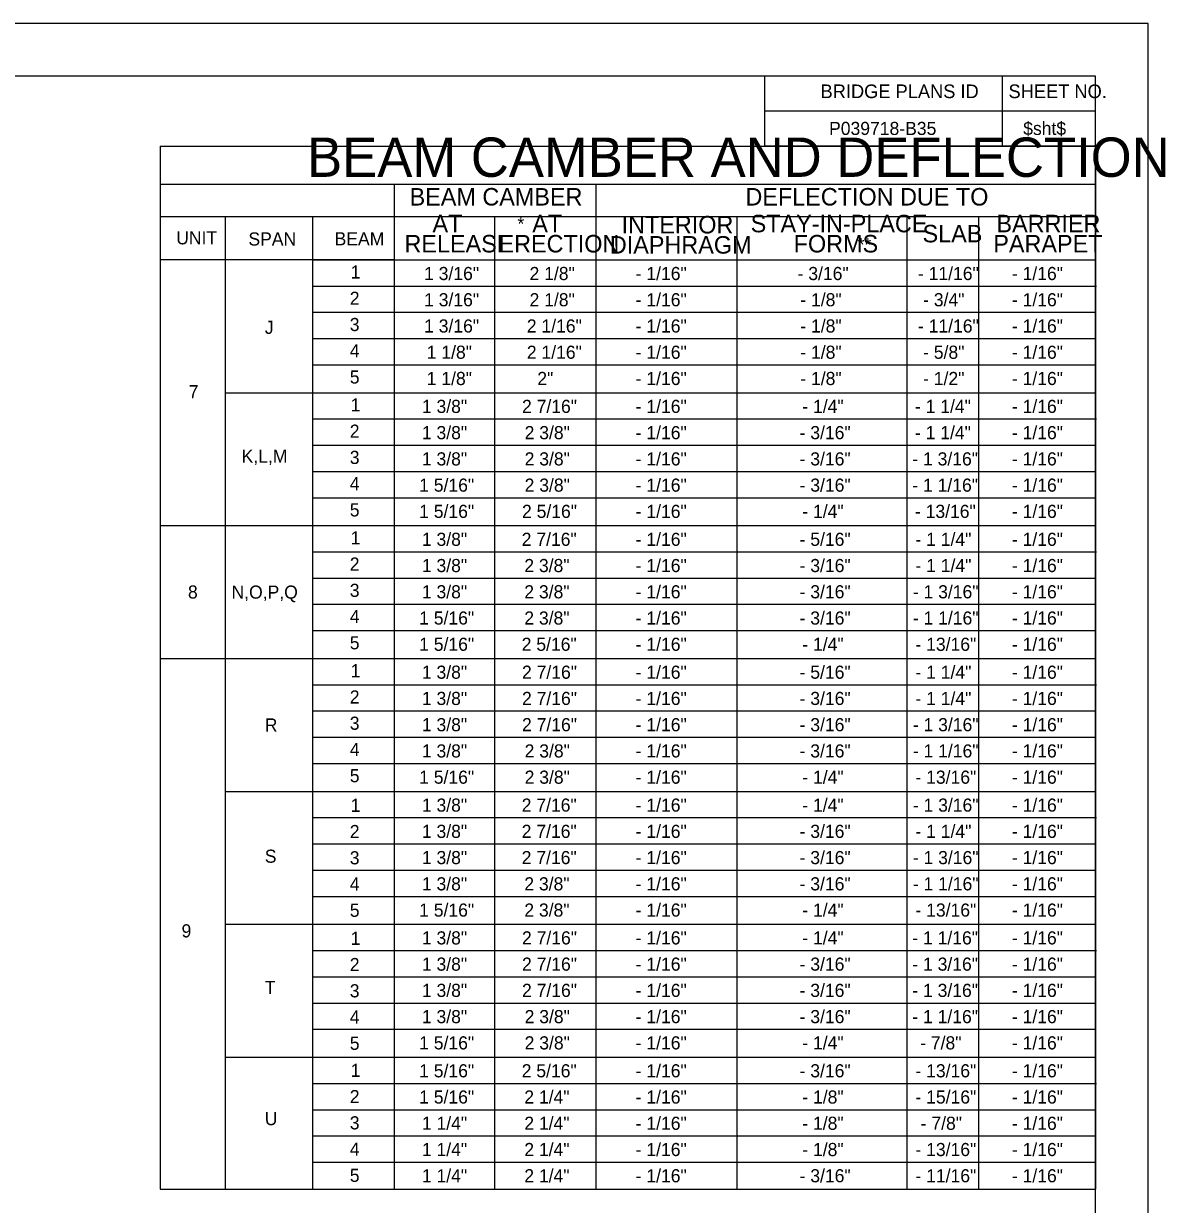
# Model space of a CAD drawing. Extents: x -50.5 to -14.4, y -5.1 to 16.9.
# Drawn here: x -25.23 to -14.35, y 5.69 to 16.93 of the extents above; entities that cross this region are included whole.
import ezdxf

# ---------------------------------------------------------------- set-up
doc = ezdxf.new("R2010")
doc.units = 0
for name, color, linetype in [('BR_BORDER LINES', 7, 'Continuous'), ('BR_TABLE LINES', 7, 'Continuous'), ('BR_TEXT', 7, 'Continuous'), ('Level 31', 7, 'Continuous')]:
    doc.layers.add(name, color=color, linetype=linetype)

msp = doc.modelspace()

# ---------------------------------------------------------------- linework, layer by layer
at = {"layer": 'BR_BORDER LINES'}
for p, q in [((-15.019, 16.434), (-48.685, 16.434)), ((-18.172, 15.767), (-18.172, 16.434)), ((-15.905, 15.767), (-15.905, 16.434)), ((-15.019, -4.566), (-15.019, 16.434)), ((-18.172, 16.104), (-15.019, 16.104)), ((-15.905, 16.104), (-15.019, 16.104)), ((-23.933, 15.767), (-15.019, 15.767)), ((-23.933, 15.767), (-23.933, 5.832)), ((-15.019, 15.767), (-18.172, 15.767)), ((-15.019, 15.767), (-15.019, 5.832)), ((-23.933, 15.403), (-15.019, 15.403)), ((-23.933, 5.832), (-15.019, 5.832))]:
    msp.add_line(p, q, dxfattribs=at)
at = {"layer": 'BR_TABLE LINES'}
for p, q in [((-21.704, 15.403), (-21.704, 5.832)), ((-19.78, 15.403), (-19.78, 5.832)), ((-23.933, 15.095), (-15.019, 15.095)), ((-23.313, 15.095), (-23.313, 5.832)), ((-22.481, 15.095), (-22.481, 5.832)), ((-20.747, 15.095), (-20.747, 5.832)), ((-18.439, 15.095), (-18.439, 5.832)), ((-16.818, 15.095), (-16.818, 5.832)), ((-16.136, 15.095), (-16.136, 5.832)), ((-21.704, 14.684), (-23.933, 14.684)), ((-22.481, 14.684), (-15.019, 14.684)), ((-22.481, 14.434), (-15.011, 14.434)), ((-22.481, 14.184), (-15.019, 14.184)), ((-22.481, 13.934), (-15.019, 13.934)), ((-22.481, 13.684), (-15.019, 13.684)), ((-23.313, 13.418), (-15.019, 13.418)), ((-22.481, 13.168), (-15.011, 13.168)), ((-22.481, 12.918), (-15.019, 12.918)), ((-22.481, 12.668), (-15.019, 12.668)), ((-22.481, 12.418), (-15.019, 12.418)), ((-23.933, 12.152), (-15.019, 12.152)), ((-22.481, 11.902), (-15.011, 11.902)), ((-22.481, 11.652), (-15.019, 11.652)), ((-22.481, 11.402), (-15.019, 11.402)), ((-22.481, 11.152), (-15.019, 11.152)), ((-23.933, 10.886), (-15.019, 10.886)), ((-22.481, 10.636), (-15.011, 10.636)), ((-22.481, 10.386), (-15.019, 10.386)), ((-22.481, 10.136), (-15.019, 10.136)), ((-22.481, 9.886), (-15.019, 9.886)), ((-23.313, 9.62), (-15.019, 9.62)), ((-22.481, 9.37), (-15.011, 9.37)), ((-22.481, 9.12), (-15.019, 9.12)), ((-22.481, 8.87), (-15.019, 8.87)), ((-22.481, 8.62), (-15.019, 8.62)), ((-23.313, 8.354), (-15.019, 8.354)), ((-22.481, 8.104), (-15.011, 8.104)), ((-22.481, 7.854), (-15.019, 7.854)), ((-22.481, 7.604), (-15.019, 7.604)), ((-22.481, 7.354), (-15.019, 7.354)), ((-23.313, 7.088), (-15.019, 7.088)), ((-22.481, 6.838), (-15.011, 6.838)), ((-22.481, 6.588), (-15.019, 6.588)), ((-22.481, 6.338), (-15.019, 6.338)), ((-22.481, 6.088), (-15.019, 6.088))]:
    msp.add_line(p, q, dxfattribs=at)
at = {"layer": 'Level 31'}
msp.add_lwpolyline([(-50.519, -5.066), (-14.519, -5.066), (-14.519, 16.934), (-50.519, 16.934)], close=True, dxfattribs=at)

# ---------------------------------------------------------------- texts
at = {"layer": 'BR_TEXT'}
for s, height, p in [('BRIDGE PLANS ID', 0.13, (-17.64, 16.224)), ('SHEET NO.', 0.13, (-15.849, 16.224)), ('P039718-B35', 0.125, (-17.559, 15.873)), ('$sht$', 0.125, (-15.709, 15.873)), ('BEAM CAMBER AND DEFLECTION', 0.375, (-22.533, 15.474)), ('BEAM CAMBER', 0.16667, (-21.556, 15.201)), ('DEFLECTION DUE TO', 0.16667, (-18.356, 15.201)), ('AT', 0.1667, (-21.338, 14.946)), ('*', 0.125, (-20.528, 14.964)), ('AT', 0.1667, (-20.387, 14.946)), ('INTERIOR', 0.1667, (-19.536, 14.935)), ('STAY-IN-PLACE', 0.16667, (-18.306, 14.946)), ('BARRIER', 0.1667, (-15.964, 14.946)), ('SLAB', 0.1667, (-16.668, 14.85)), ('RELEASE', 0.1667, (-21.605, 14.754)), ('ERECTION', 0.1667, (-20.709, 14.754)), ('DIAPHRAGM', 0.1667, (-19.648, 14.743)), ('FORMS', 0.1667, (-17.896, 14.754)), ('**', 0.125, (-17.287, 14.766)), ('PARAPET', 0.1667, (-15.994, 14.754)), ('1', 0.125, (-22.118, 14.505)), ('1 3/16"', 0.125, (-21.418, 14.491)), ('2 1/8"', 0.125, (-20.413, 14.491)), ('- 1/16"', 0.125, (-19.402, 14.491)), ('- 3/16"', 0.125, (-17.859, 14.491)), ('- 11/16"', 0.125, (-16.712, 14.491)), ('- 1/16"', 0.125, (-15.817, 14.491)), ('2', 0.125, (-22.126, 14.255)), ('1 3/16"', 0.125, (-21.418, 14.241)), ('2 1/8"', 0.125, (-20.413, 14.241)), ('- 1/16"', 0.125, (-19.402, 14.241)), ('- 1/8"', 0.125, (-17.833, 14.241)), ('- 3/4"', 0.125, (-16.663, 14.241)), ('- 1/16"', 0.125, (-15.817, 14.241)), ('3', 0.125, (-22.126, 14.005)), ('1 3/16"', 0.125, (-21.418, 13.991)), ('2 1/16"', 0.125, (-20.439, 13.991)), ('- 1/16"', 0.125, (-19.402, 13.991)), ('- 1/8"', 0.125, (-17.833, 13.991)), ('- 11/16"', 0.125, (-16.712, 13.991)), ('- 1/16"', 0.125, (-15.817, 13.991)), ('4', 0.125, (-22.126, 13.755)), ('1 1/8"', 0.125, (-21.393, 13.741)), ('2 1/16"', 0.125, (-20.439, 13.741)), ('- 1/16"', 0.125, (-19.402, 13.741)), ('- 1/8"', 0.125, (-17.833, 13.741)), ('- 5/8"', 0.125, (-16.663, 13.741)), ('- 1/16"', 0.125, (-15.817, 13.741)), ('5', 0.125, (-22.126, 13.505)), ('1 1/8"', 0.125, (-21.393, 13.491)), ('2"', 0.125, (-20.339, 13.491)), ('- 1/16"', 0.125, (-19.402, 13.491)), ('- 1/8"', 0.125, (-17.833, 13.491)), ('- 1/2"', 0.125, (-16.663, 13.491)), ('- 1/16"', 0.125, (-15.817, 13.491)), ('1', 0.125, (-22.118, 13.239)), ('1 3/8"', 0.125, (-21.439, 13.225)), ('2 7/16"', 0.125, (-20.485, 13.225)), ('- 1/16"', 0.125, (-19.402, 13.225)), ('- 1/4"', 0.125, (-17.814, 13.225)), ('- 1 1/4"', 0.125, (-16.741, 13.225)), ('- 1/16"', 0.125, (-15.817, 13.225)), ('2', 0.125, (-22.126, 12.989)), ('1 3/8"', 0.125, (-21.439, 12.975)), ('2 3/8"', 0.125, (-20.46, 12.975)), ('- 1/16"', 0.125, (-19.402, 12.975)), ('- 3/16"', 0.125, (-17.84, 12.975)), ('- 1 1/4"', 0.125, (-16.741, 12.975)), ('- 1/16"', 0.125, (-15.817, 12.975)), ('3', 0.125, (-22.126, 12.739)), ('1 3/8"', 0.125, (-21.439, 12.725)), ('2 3/8"', 0.125, (-20.46, 12.725)), ('- 1/16"', 0.125, (-19.402, 12.725)), ('- 3/16"', 0.125, (-17.84, 12.725)), ('- 1 3/16"', 0.125, (-16.766, 12.725)), ('- 1/16"', 0.125, (-15.817, 12.725)), ('4', 0.125, (-22.126, 12.489)), ('1 5/16"', 0.125, (-21.465, 12.475)), ('2 3/8"', 0.125, (-20.46, 12.475)), ('- 1/16"', 0.125, (-19.402, 12.475)), ('- 3/16"', 0.125, (-17.84, 12.475)), ('- 1 1/16"', 0.125, (-16.766, 12.475)), ('- 1/16"', 0.125, (-15.817, 12.475)), ('5', 0.125, (-22.126, 12.239)), ('1 5/16"', 0.125, (-21.465, 12.225)), ('2 5/16"', 0.125, (-20.485, 12.225)), ('- 1/16"', 0.125, (-19.402, 12.225)), ('- 1/4"', 0.125, (-17.814, 12.225)), ('- 13/16"', 0.125, (-16.741, 12.225)), ('- 1/16"', 0.125, (-15.817, 12.225)), ('1', 0.125, (-22.118, 11.973)), ('1 3/8"', 0.125, (-21.439, 11.959)), ('2 7/16"', 0.125, (-20.488, 11.959)), ('- 1/16"', 0.125, (-19.402, 11.959)), ('- 5/16"', 0.125, (-17.84, 11.959)), ('- 1 1/4"', 0.125, (-16.736, 11.959)), ('- 1/16"', 0.125, (-15.817, 11.959)), ('2', 0.125, (-22.126, 11.723)), ('1 3/8"', 0.125, (-21.439, 11.709)), ('2 3/8"', 0.125, (-20.463, 11.709)), ('- 1/16"', 0.125, (-19.402, 11.709)), ('- 3/16"', 0.125, (-17.84, 11.709)), ('- 1 1/4"', 0.125, (-16.736, 11.709)), ('- 1/16"', 0.125, (-15.817, 11.709)), ('3', 0.125, (-22.126, 11.473)), ('1 3/8"', 0.125, (-21.439, 11.459)), ('2 3/8"', 0.125, (-20.463, 11.459)), ('- 1/16"', 0.125, (-19.402, 11.459)), ('- 3/16"', 0.125, (-17.84, 11.459)), ('- 1 3/16"', 0.125, (-16.761, 11.459)), ('- 1/16"', 0.125, (-15.817, 11.459)), ('4', 0.125, (-22.126, 11.223)), ('1 5/16"', 0.125, (-21.465, 11.209)), ('2 3/8"', 0.125, (-20.463, 11.209)), ('- 1/16"', 0.125, (-19.402, 11.209)), ('- 3/16"', 0.125, (-17.84, 11.209)), ('- 1 1/16"', 0.125, (-16.761, 11.209)), ('- 1/16"', 0.125, (-15.817, 11.209)), ('5', 0.125, (-22.126, 10.973)), ('1 5/16"', 0.125, (-21.465, 10.959)), ('2 5/16"', 0.125, (-20.488, 10.959)), ('- 1/16"', 0.125, (-19.402, 10.959)), ('- 1/4"', 0.125, (-17.814, 10.959)), ('- 13/16"', 0.125, (-16.736, 10.959)), ('- 1/16"', 0.125, (-15.817, 10.959)), ('1', 0.125, (-22.118, 10.707)), ('1 3/8"', 0.125, (-21.439, 10.693)), ('2 7/16"', 0.125, (-20.485, 10.693)), ('- 1/16"', 0.125, (-19.402, 10.693)), ('- 5/16"', 0.125, (-17.84, 10.693)), ('- 1 1/4"', 0.125, (-16.736, 10.693)), ('- 1/16"', 0.125, (-15.817, 10.693)), ('2', 0.125, (-22.126, 10.457)), ('1 3/8"', 0.125, (-21.439, 10.443)), ('2 7/16"', 0.125, (-20.485, 10.443)), ('- 1/16"', 0.125, (-19.402, 10.443)), ('- 3/16"', 0.125, (-17.84, 10.443)), ('- 1 1/4"', 0.125, (-16.736, 10.443)), ('- 1/16"', 0.125, (-15.817, 10.443)), ('3', 0.125, (-22.126, 10.207)), ('1 3/8"', 0.125, (-21.439, 10.193)), ('2 7/16"', 0.125, (-20.485, 10.193)), ('- 1/16"', 0.125, (-19.402, 10.193)), ('- 3/16"', 0.125, (-17.84, 10.193)), ('- 1 3/16"', 0.125, (-16.761, 10.193)), ('- 1/16"', 0.125, (-15.817, 10.193)), ('4', 0.125, (-22.126, 9.957)), ('1 3/8"', 0.125, (-21.439, 9.943)), ('2 3/8"', 0.125, (-20.46, 9.943)), ('- 1/16"', 0.125, (-19.402, 9.943)), ('- 3/16"', 0.125, (-17.84, 9.943)), ('- 1 1/16"', 0.125, (-16.761, 9.943)), ('- 1/16"', 0.125, (-15.817, 9.943)), ('5', 0.125, (-22.126, 9.707)), ('1 5/16"', 0.125, (-21.465, 9.693)), ('2 3/8"', 0.125, (-20.46, 9.693)), ('- 1/16"', 0.125, (-19.402, 9.693)), ('- 1/4"', 0.125, (-17.814, 9.693)), ('- 13/16"', 0.125, (-16.736, 9.693)), ('- 1/16"', 0.125, (-15.817, 9.693)), ('1', 0.125, (-22.118, 9.425)), ('1 3/8"', 0.125, (-21.439, 9.427)), ('2 7/16"', 0.125, (-20.488, 9.427)), ('- 1/16"', 0.125, (-19.402, 9.427)), ('- 1/4"', 0.125, (-17.814, 9.427)), ('- 1 3/16"', 0.125, (-16.761, 9.427)), ('- 1/16"', 0.125, (-15.817, 9.427)), ('2', 0.125, (-22.126, 9.175)), ('1 3/8"', 0.125, (-21.439, 9.177)), ('2 7/16"', 0.125, (-20.488, 9.177)), ('- 1/16"', 0.125, (-19.402, 9.177)), ('- 3/16"', 0.125, (-17.84, 9.177)), ('- 1 1/4"', 0.125, (-16.736, 9.177)), ('- 1/16"', 0.125, (-15.817, 9.177)), ('3', 0.125, (-22.126, 8.925)), ('1 3/8"', 0.125, (-21.439, 8.927)), ('2 7/16"', 0.125, (-20.488, 8.927)), ('- 1/16"', 0.125, (-19.402, 8.927)), ('- 3/16"', 0.125, (-17.84, 8.927)), ('- 1 3/16"', 0.125, (-16.761, 8.927)), ('- 1/16"', 0.125, (-15.817, 8.927)), ('4', 0.125, (-22.126, 8.675)), ('1 3/8"', 0.125, (-21.439, 8.677)), ('2 3/8"', 0.125, (-20.463, 8.677)), ('- 1/16"', 0.125, (-19.402, 8.677)), ('- 3/16"', 0.125, (-17.84, 8.677)), ('- 1 1/16"', 0.125, (-16.761, 8.677)), ('- 1/16"', 0.125, (-15.817, 8.677)), ('5', 0.125, (-22.126, 8.425)), ('1 5/16"', 0.125, (-21.465, 8.427)), ('2 3/8"', 0.125, (-20.463, 8.427)), ('- 1/16"', 0.125, (-19.402, 8.427)), ('- 1/4"', 0.125, (-17.814, 8.427)), ('- 13/16"', 0.125, (-16.736, 8.427)), ('- 1/16"', 0.125, (-15.817, 8.427)), ('1', 0.125, (-22.118, 8.158)), ('1 3/8"', 0.125, (-21.439, 8.162)), ('2 7/16"', 0.125, (-20.485, 8.162)), ('- 1/16"', 0.125, (-19.402, 8.162)), ('- 1/4"', 0.125, (-17.814, 8.162)), ('- 1 1/16"', 0.125, (-16.766, 8.162)), ('- 1/16"', 0.125, (-15.817, 8.162)), ('2', 0.125, (-22.126, 7.908)), ('1 3/8"', 0.125, (-21.439, 7.912)), ('2 7/16"', 0.125, (-20.485, 7.912)), ('- 1/16"', 0.125, (-19.402, 7.912)), ('- 3/16"', 0.125, (-17.84, 7.912)), ('- 1 3/16"', 0.125, (-16.766, 7.912)), ('- 1/16"', 0.125, (-15.817, 7.912)), ('3', 0.125, (-22.126, 7.658)), ('1 3/8"', 0.125, (-21.439, 7.662)), ('2 7/16"', 0.125, (-20.485, 7.662)), ('- 1/16"', 0.125, (-19.402, 7.662)), ('- 3/16"', 0.125, (-17.84, 7.662)), ('- 1 3/16"', 0.125, (-16.766, 7.662)), ('- 1/16"', 0.125, (-15.817, 7.662)), ('1 3/8"', 0.125, (-21.439, 7.412)), ('2 3/8"', 0.125, (-20.46, 7.412)), ('- 1/16"', 0.125, (-19.402, 7.412)), ('- 3/16"', 0.125, (-17.84, 7.412)), ('- 1 1/16"', 0.125, (-16.766, 7.412)), ('- 1/16"', 0.125, (-15.817, 7.412)), ('4', 0.125, (-22.126, 7.408)), ('5', 0.125, (-22.126, 7.158)), ('1 5/16"', 0.125, (-21.465, 7.162)), ('2 3/8"', 0.125, (-20.46, 7.162)), ('- 1/16"', 0.125, (-19.402, 7.162)), ('- 1/4"', 0.125, (-17.814, 7.162)), ('- 7/8"', 0.125, (-16.691, 7.162)), ('- 1/16"', 0.125, (-15.817, 7.162)), ('1', 0.125, (-22.118, 6.9)), ('1 5/16"', 0.125, (-21.465, 6.896)), ('2 5/16"', 0.125, (-20.488, 6.896)), ('- 1/16"', 0.125, (-19.402, 6.896)), ('- 3/16"', 0.125, (-17.84, 6.896)), ('- 13/16"', 0.125, (-16.736, 6.896)), ('- 1/16"', 0.125, (-15.817, 6.896)), ('2', 0.125, (-22.126, 6.65)), ('1 5/16"', 0.125, (-21.465, 6.646)), ('2 1/4"', 0.125, (-20.463, 6.646)), ('- 1/16"', 0.125, (-19.402, 6.646)), ('- 1/8"', 0.125, (-17.814, 6.646)), ('- 15/16"', 0.125, (-16.736, 6.646)), ('- 1/16"', 0.125, (-15.817, 6.646)), ('3', 0.125, (-22.126, 6.4)), ('1 1/4"', 0.125, (-21.439, 6.396)), ('2 1/4"', 0.125, (-20.463, 6.396)), ('- 1/16"', 0.125, (-19.402, 6.396)), ('- 1/8"', 0.125, (-17.814, 6.396)), ('- 7/8"', 0.125, (-16.686, 6.396)), ('- 1/16"', 0.125, (-15.817, 6.396)), ('4', 0.125, (-22.126, 6.15)), ('1 1/4"', 0.125, (-21.439, 6.146)), ('2 1/4"', 0.125, (-20.463, 6.146)), ('- 1/16"', 0.125, (-19.402, 6.146)), ('- 1/8"', 0.125, (-17.814, 6.146)), ('- 13/16"', 0.125, (-16.736, 6.146)), ('- 1/16"', 0.125, (-15.817, 6.146)), ('5', 0.125, (-22.126, 5.9)), ('1 1/4"', 0.125, (-21.439, 5.896)), ('2 1/4"', 0.125, (-20.463, 5.896)), ('- 1/16"', 0.125, (-19.402, 5.896)), ('- 3/16"', 0.125, (-17.84, 5.896)), ('- 11/16"', 0.125, (-16.736, 5.896)), ('- 1/16"', 0.125, (-15.817, 5.896))]:
    msp.add_text(s, height=height, dxfattribs=at).set_placement(p)
for s, p in [('UNIT', (-23.78, 14.831)), ('SPAN', (-23.092, 14.82)), ('BEAM', (-22.271, 14.822)), ('J', (-22.936, 13.978)), ('7', (-23.661, 13.365)), ('K,L,M', (-23.157, 12.751)), ('8', (-23.668, 11.457)), ('N,O,P,Q', (-23.253, 11.456)), ('R', (-22.936, 10.19)), ('S', (-22.936, 8.94)), ('9', (-23.729, 8.229)), ('T', (-22.936, 7.69)), ('U', (-22.936, 6.44))]:
    msp.add_text(s, height=0.125, rotation=360, dxfattribs=at).set_placement(p)

doc.saveas('drawing.dxf')
